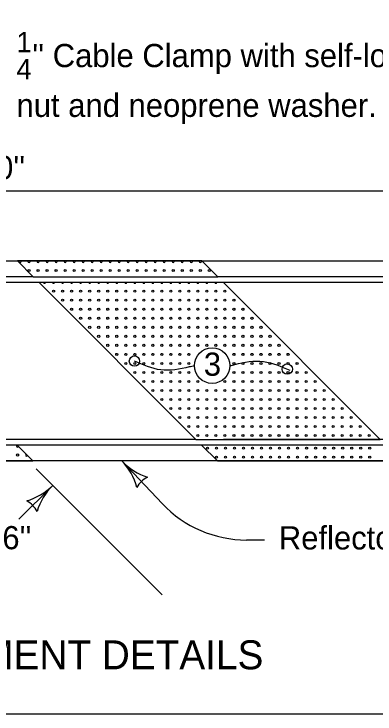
# Model space of a CAD drawing. Extents: x 228 to 3572, y -1307 to 1277.
# Drawn here: x 2207.4 to 2456.6, y -1020 to -537.2 of the extents above; entities that cross this region are included whole.
import ezdxf

# ---------------------------------------------------------------- set-up
doc = ezdxf.new("R2010")
doc.units = 0
for name, color, linetype in [('dsnStdBorder', 7, 'Continuous'), ('dsnStdDimension', 7, 'Continuous'), ('Level 2', 7, 'Continuous'), ('Level 3', 7, 'Continuous')]:
    doc.layers.add(name, color=color, linetype=linetype)

msp = doc.modelspace()

# ---------------------------------------------------------------- linework, layer by layer
at = {"layer": 'dsnStdBorder'}
msp.add_lwpolyline([(332.48, 990.01), (3467.48, 990.01), (3467.48, -1019.99), (332.48, -1019.99)], close=True, dxfattribs=at)
at = {"layer": 'dsnStdDimension'}
for p, q in [((2559.99, -659.46), (1827.99, -659.46)), ((2309.83, -874.95), (2281.94, -845.46)), ((2309.76, -937.89), (2222.85, -850.98)), ((2210.76, -885.69), (2234.16, -862.29)), ((2380.35, -899.98), (2367.96, -899.98))]:
    msp.add_line(p, q, dxfattribs=at)
for centre, radius, start, end in [((2313.31, -815.79), 43.18, 223.3968, 251.4693), ((2250.56, -875.12), 43.18, 15.3243, 43.3968), ((2306.81, -871.76), 16.68, 115.6635, 151.1302), ((2203.63, -831.76), 43.18, 286.9275, 315), ((2264.69, -892.83), 43.18, 135, 163.0725), ((2208.56, -887.89), 16.68, 27.2667, 62.7334), ((2367.95, -819.98), 80, 223.3989, 270)]:
    msp.add_arc(centre, radius, start, end, dxfattribs=at)
at = {"layer": 'Level 2'}
for p, q in [((2337.11, -707.46), (2209.83, -707.46)), ((2209.83, -707.46), (2220.73, -718.36)), ((2220.55, -707.46), (2347.83, -707.46)), ((2348.01, -718.36), (2337.11, -707.46)), ((2220.73, -718.36), (2093.45, -718.36)), ((2220.73, -718.36), (2348.01, -718.36)), ((2475.29, -718.36), (2348.01, -718.36)), ((2224.73, -722.36), (2097.45, -722.36)), ((2352.01, -722.36), (2224.73, -722.36)), ((2224.73, -722.36), (2332.93, -830.56)), ((2460.21, -830.56), (2352.01, -722.36)), ((2479.29, -722.36), (2352.01, -722.36)), ((2209.65, -834.56), (2082.37, -834.56)), ((2336.93, -834.56), (2093.45, -834.56)), ((2332.93, -830.56), (2097.45, -830.56)), ((2220.55, -845.46), (2209.65, -834.56)), ((2332.93, -830.56), (2460.21, -830.56)), ((2464.21, -834.56), (2336.93, -834.56)), ((2336.93, -834.56), (2347.83, -845.46)), ((2527.59, -834.56), (2348.01, -834.56)), ((2527.59, -830.56), (2352.01, -830.56)), ((2209.83, -845.46), (1960.08, -845.46)), ((2093.27, -845.46), (2220.55, -845.46)), ((2464.39, -845.46), (2337.11, -845.46)), ((2347.83, -845.46), (2475.11, -845.46))]:
    msp.add_line(p, q, dxfattribs=at)
msp.add_lwpolyline([(1827.99, -707.46), (2559.99, -707.46), (2559.99, -845.46), (1827.99, -845.46)], close=True, dxfattribs=at)
for centre, radius in [((2217.8, -714.12), 0.711), ((2224.03, -714.12), 0.711), ((2230.25, -714.12), 0.711), ((2236.47, -714.12), 0.711), ((2242.69, -714.12), 0.711), ((2248.92, -714.12), 0.711), ((2255.14, -714.12), 0.711), ((2261.36, -714.12), 0.711), ((2267.58, -714.12), 0.711), ((2273.81, -714.12), 0.711), ((2280.03, -714.12), 0.711), ((2286.25, -714.12), 0.711), ((2292.47, -714.12), 0.711), ((2298.7, -714.12), 0.711), ((2304.92, -714.12), 0.711), ((2311.14, -714.12), 0.711), ((2317.36, -714.12), 0.711), ((2323.58, -714.12), 0.711), ((2329.81, -714.12), 0.711), ((2336.03, -714.12), 0.711), ((2342.25, -714.12), 0.711), ((2234.78, -728.38), 0.711), ((2241, -728.38), 0.711), ((2247.22, -728.38), 0.711), ((2253.44, -728.38), 0.711), ((2259.67, -728.38), 0.711), ((2265.89, -728.38), 0.711), ((2272.11, -728.38), 0.711), ((2278.33, -728.38), 0.711), ((2284.56, -728.38), 0.711), ((2290.78, -728.38), 0.711), ((2297, -728.38), 0.711), ((2303.22, -728.38), 0.711), ((2309.45, -728.38), 0.711), ((2315.67, -728.38), 0.711), ((2321.89, -728.38), 0.711), ((2328.11, -728.38), 0.711), ((2334.34, -728.38), 0.711), ((2340.56, -728.38), 0.711), ((2346.78, -728.38), 0.711), ((2353, -728.38), 0.711), ((2241, -734.6), 0.711), ((2247.22, -734.6), 0.711), ((2253.44, -734.6), 0.711), ((2259.67, -734.6), 0.711), ((2265.89, -734.6), 0.711), ((2272.11, -734.6), 0.711), ((2278.33, -734.6), 0.711), ((2284.56, -734.6), 0.711), ((2290.78, -734.6), 0.711), ((2297, -734.6), 0.711), ((2303.22, -734.6), 0.711), ((2309.45, -734.6), 0.711), ((2315.67, -734.6), 0.711), ((2321.89, -734.6), 0.711), ((2328.11, -734.6), 0.711), ((2334.34, -734.6), 0.711), ((2340.56, -734.6), 0.711), ((2346.78, -734.6), 0.711), ((2353, -734.6), 0.711), ((2359.23, -734.6), 0.711), ((2247.22, -740.83), 0.711), ((2253.44, -740.83), 0.711), ((2259.67, -740.83), 0.711), ((2265.89, -740.83), 0.711), ((2272.11, -740.83), 0.711), ((2278.33, -740.83), 0.711), ((2284.56, -740.83), 0.711), ((2290.78, -740.83), 0.711), ((2297, -740.83), 0.711), ((2303.22, -740.83), 0.711), ((2309.45, -740.83), 0.711), ((2315.67, -740.83), 0.711), ((2321.89, -740.83), 0.711), ((2328.11, -740.83), 0.711), ((2334.34, -740.83), 0.711), ((2340.56, -740.83), 0.711), ((2346.78, -740.83), 0.711), ((2353, -740.83), 0.711), ((2359.23, -740.83), 0.711), ((2365.45, -740.83), 0.711), ((2253.44, -747.05), 0.711), ((2259.67, -747.05), 0.711), ((2265.89, -747.05), 0.711), ((2272.11, -747.05), 0.711), ((2278.33, -747.05), 0.711), ((2284.56, -747.05), 0.711), ((2290.78, -747.05), 0.711), ((2297, -747.05), 0.711), ((2303.22, -747.05), 0.711), ((2309.45, -747.05), 0.711), ((2315.67, -747.05), 0.711), ((2321.89, -747.05), 0.711), ((2328.11, -747.05), 0.711), ((2334.34, -747.05), 0.711), ((2340.56, -747.05), 0.711), ((2346.78, -747.05), 0.711), ((2353, -747.05), 0.711), ((2359.23, -747.05), 0.711), ((2365.45, -747.05), 0.711), ((2371.67, -747.05), 0.711), ((2259.67, -753.27), 0.711), ((2265.89, -753.27), 0.711), ((2272.11, -753.27), 0.711), ((2278.33, -753.27), 0.711), ((2284.56, -753.27), 0.711), ((2290.78, -753.27), 0.711), ((2297, -753.27), 0.711), ((2303.22, -753.27), 0.711), ((2309.45, -753.27), 0.711), ((2315.67, -753.27), 0.711), ((2321.89, -753.27), 0.711), ((2328.11, -753.27), 0.711), ((2334.34, -753.27), 0.711), ((2340.56, -753.27), 0.711), ((2346.78, -753.27), 0.711), ((2353, -753.27), 0.711), ((2359.23, -753.27), 0.711), ((2365.45, -753.27), 0.711), ((2371.67, -753.27), 0.711), ((2377.89, -753.27), 0.711), ((2265.89, -759.49), 0.711), ((2272.11, -759.49), 0.711), ((2278.33, -759.49), 0.711), ((2284.56, -759.49), 0.711), ((2290.78, -759.49), 0.711), ((2297, -759.49), 0.711), ((2303.22, -759.49), 0.711), ((2309.45, -759.49), 0.711), ((2315.67, -759.49), 0.711), ((2321.89, -759.49), 0.711), ((2328.11, -759.49), 0.711), ((2334.34, -759.49), 0.711), ((2340.56, -759.49), 0.711), ((2346.78, -759.49), 0.711), ((2353, -759.49), 0.711), ((2359.23, -759.49), 0.711), ((2365.45, -759.49), 0.711), ((2371.67, -759.49), 0.711), ((2377.89, -759.49), 0.711), ((2384.12, -759.49), 0.711), ((2272.11, -765.72), 0.711), ((2278.33, -765.72), 0.711), ((2284.56, -765.72), 0.711), ((2290.78, -765.72), 0.711), ((2297, -765.72), 0.711), ((2303.22, -765.72), 0.711), ((2309.45, -765.72), 0.711), ((2315.67, -765.72), 0.711), ((2321.89, -765.72), 0.711), ((2328.11, -765.72), 0.711), ((2344.17, -779.7), 12.25), ((2334.34, -765.72), 0.711), ((2340.56, -765.72), 0.711), ((2346.78, -765.72), 0.711), ((2353, -765.72), 0.711), ((2359.23, -765.72), 0.711), ((2365.45, -765.72), 0.711), ((2371.67, -765.72), 0.711), ((2377.89, -765.72), 0.711), ((2384.12, -765.72), 0.711), ((2390.34, -765.72), 0.711), ((2278.33, -771.94), 0.711), ((2284.56, -771.94), 0.711), ((2290.78, -771.94), 0.711), ((2297, -771.94), 0.711), ((2303.22, -771.94), 0.711), ((2309.45, -771.94), 0.711), ((2315.67, -771.94), 0.711), ((2321.89, -771.94), 0.711), ((2328.11, -771.94), 0.711), ((2359.23, -771.94), 0.711), ((2365.45, -771.94), 0.711), ((2371.67, -771.94), 0.711), ((2377.89, -771.94), 0.711), ((2384.12, -771.94), 0.711), ((2390.34, -771.94), 0.711), ((2396.56, -771.94), 0.711), ((2290.58, -776.56), 3.56), ((2284.56, -778.16), 0.711), ((2290.76, -778.21), 0.711), ((2297, -778.16), 0.711), ((2303.22, -778.16), 0.711), ((2309.45, -778.16), 0.711), ((2315.67, -778.16), 0.711), ((2321.89, -778.16), 0.711), ((2328.11, -778.16), 0.711), ((2359.23, -778.16), 0.711), ((2365.45, -778.16), 0.711), ((2371.67, -778.16), 0.711), ((2377.89, -778.16), 0.711), ((2384.12, -778.16), 0.711), ((2390.34, -778.16), 0.711), ((2396.04, -782.04), 3.56), ((2396.56, -778.16), 0.711), ((2402.78, -778.16), 0.711), ((2290.78, -784.38), 0.711), ((2297, -784.38), 0.711), ((2303.22, -784.38), 0.711), ((2309.45, -784.38), 0.711), ((2315.67, -784.38), 0.711), ((2321.89, -784.38), 0.711), ((2328.11, -784.38), 0.711), ((2359.23, -784.38), 0.711), ((2365.45, -784.38), 0.711), ((2371.67, -784.38), 0.711), ((2377.89, -784.38), 0.711), ((2384.12, -784.38), 0.711), ((2390.34, -784.38), 0.711), ((2396.54, -784.43), 0.711), ((2402.78, -784.38), 0.711), ((2409, -784.38), 0.711), ((2297, -790.61), 0.711), ((2303.22, -790.61), 0.711), ((2309.45, -790.61), 0.711), ((2315.67, -790.61), 0.711), ((2321.89, -790.61), 0.711), ((2328.11, -790.61), 0.711), ((2334.34, -790.61), 0.711), ((2353, -790.61), 0.711), ((2359.23, -790.61), 0.711), ((2365.45, -790.61), 0.711), ((2371.67, -790.61), 0.711), ((2377.89, -790.61), 0.711), ((2384.12, -790.61), 0.711), ((2390.34, -790.61), 0.711), ((2396.56, -790.61), 0.711), ((2402.78, -790.61), 0.711), ((2409, -790.61), 0.711), ((2415.23, -790.61), 0.711), ((2303.22, -796.83), 0.711), ((2309.45, -796.83), 0.711), ((2315.67, -796.83), 0.711), ((2321.89, -796.83), 0.711), ((2328.11, -796.83), 0.711), ((2334.34, -796.83), 0.711), ((2340.56, -796.83), 0.711), ((2346.78, -796.83), 0.711), ((2353, -796.83), 0.711), ((2359.23, -796.83), 0.711), ((2365.45, -796.83), 0.711), ((2371.67, -796.83), 0.711), ((2377.89, -796.83), 0.711), ((2384.12, -796.83), 0.711), ((2390.34, -796.83), 0.711), ((2396.56, -796.83), 0.711), ((2402.78, -796.83), 0.711), ((2409, -796.83), 0.711), ((2415.23, -796.83), 0.711), ((2421.45, -796.83), 0.711), ((2309.45, -803.05), 0.711), ((2315.67, -803.05), 0.711), ((2321.89, -803.05), 0.711), ((2328.11, -803.05), 0.711), ((2334.34, -803.05), 0.711), ((2340.56, -803.05), 0.711), ((2346.78, -803.05), 0.711), ((2353, -803.05), 0.711), ((2359.23, -803.05), 0.711), ((2365.45, -803.05), 0.711), ((2371.67, -803.05), 0.711), ((2377.89, -803.05), 0.711), ((2384.12, -803.05), 0.711), ((2390.34, -803.05), 0.711), ((2396.56, -803.05), 0.711), ((2402.78, -803.05), 0.711), ((2409, -803.05), 0.711), ((2415.23, -803.05), 0.711), ((2421.45, -803.05), 0.711), ((2427.67, -803.05), 0.711), ((2315.67, -809.27), 0.711), ((2321.89, -809.27), 0.711), ((2328.11, -809.27), 0.711), ((2334.34, -809.27), 0.711), ((2340.56, -809.27), 0.711), ((2346.78, -809.27), 0.711), ((2353, -809.27), 0.711), ((2359.23, -809.27), 0.711), ((2365.45, -809.27), 0.711), ((2371.67, -809.27), 0.711), ((2377.89, -809.27), 0.711), ((2384.12, -809.27), 0.711), ((2390.34, -809.27), 0.711), ((2396.56, -809.27), 0.711), ((2402.78, -809.27), 0.711), ((2409, -809.27), 0.711), ((2415.23, -809.27), 0.711), ((2421.45, -809.27), 0.711), ((2427.67, -809.27), 0.711), ((2433.89, -809.27), 0.711), ((2321.89, -815.5), 0.711), ((2328.11, -815.5), 0.711), ((2334.34, -815.5), 0.711), ((2340.56, -815.5), 0.711), ((2346.78, -815.5), 0.711), ((2353, -815.5), 0.711), ((2359.23, -815.5), 0.711), ((2365.45, -815.5), 0.711), ((2371.67, -815.5), 0.711), ((2377.89, -815.5), 0.711), ((2384.12, -815.5), 0.711), ((2390.34, -815.5), 0.711), ((2396.56, -815.5), 0.711), ((2402.78, -815.5), 0.711), ((2409, -815.5), 0.711), ((2415.23, -815.5), 0.711), ((2421.45, -815.5), 0.711), ((2427.67, -815.5), 0.711), ((2433.89, -815.5), 0.711), ((2440.12, -815.5), 0.711), ((2328.11, -821.72), 0.711), ((2334.34, -821.72), 0.711), ((2340.56, -821.72), 0.711), ((2346.78, -821.72), 0.711), ((2353, -821.72), 0.711), ((2359.23, -821.72), 0.711), ((2365.45, -821.72), 0.711), ((2371.67, -821.72), 0.711), ((2377.89, -821.72), 0.711), ((2384.12, -821.72), 0.711), ((2390.34, -821.72), 0.711), ((2396.56, -821.72), 0.711), ((2402.78, -821.72), 0.711), ((2409, -821.72), 0.711), ((2415.23, -821.72), 0.711), ((2421.45, -821.72), 0.711), ((2427.67, -821.72), 0.711), ((2433.89, -821.72), 0.711), ((2440.12, -821.72), 0.711), ((2446.34, -821.72), 0.711), ((2334.34, -827.94), 0.711), ((2340.56, -827.94), 0.711), ((2346.78, -827.94), 0.711), ((2353, -827.94), 0.711), ((2359.23, -827.94), 0.711), ((2365.45, -827.94), 0.711), ((2371.67, -827.94), 0.711), ((2377.89, -827.94), 0.711), ((2384.12, -827.94), 0.711), ((2390.34, -827.94), 0.711), ((2396.56, -827.94), 0.711), ((2402.78, -827.94), 0.711), ((2409, -827.94), 0.711), ((2415.23, -827.94), 0.711), ((2421.45, -827.94), 0.711), ((2427.67, -827.94), 0.711), ((2433.89, -827.94), 0.711), ((2440.12, -827.94), 0.711), ((2446.34, -827.94), 0.711), ((2452.56, -827.94), 0.711), ((2340.93, -836.67), 0.711), ((2347.15, -836.67), 0.711), ((2353.37, -836.67), 0.711), ((2359.6, -836.67), 0.711), ((2365.82, -836.67), 0.711), ((2372.04, -836.67), 0.711), ((2378.26, -836.67), 0.711), ((2384.49, -836.67), 0.711), ((2390.71, -836.67), 0.711), ((2396.93, -836.67), 0.711), ((2403.15, -836.67), 0.711), ((2409.38, -836.67), 0.711), ((2415.6, -836.67), 0.711), ((2421.82, -836.67), 0.711), ((2428.04, -836.67), 0.711), ((2434.27, -836.67), 0.711), ((2440.49, -836.67), 0.711), ((2446.71, -836.67), 0.711), ((2452.93, -836.67), 0.711), ((2209.95, -841.35), 0.711), ((2347.15, -842.9), 0.711), ((2353.37, -842.9), 0.711), ((2359.6, -842.9), 0.711), ((2365.82, -842.9), 0.711), ((2372.04, -842.9), 0.711), ((2378.26, -842.9), 0.711), ((2384.49, -842.9), 0.711), ((2390.71, -842.9), 0.711), ((2396.93, -842.9), 0.711), ((2403.15, -842.9), 0.711), ((2409.38, -842.9), 0.711), ((2415.6, -842.9), 0.711), ((2421.82, -842.9), 0.711), ((2428.04, -842.9), 0.711), ((2434.27, -842.9), 0.711), ((2440.49, -842.9), 0.711), ((2446.71, -842.9), 0.711), ((2452.93, -842.9), 0.711)]:
    msp.add_circle(centre, radius, dxfattribs=at)
for centre, start, end in [((2211.58, -707.9), 141.3696, 38.6304), ((2217.8, -707.9), 141.3696, 38.6304), ((2224.03, -707.9), 141.3696, 38.6304), ((2230.25, -707.9), 141.3696, 38.6304), ((2236.47, -707.9), 141.3696, 38.6304), ((2242.69, -707.9), 141.3696, 38.6304), ((2248.92, -707.9), 141.3696, 38.6304), ((2255.14, -707.9), 141.3696, 38.6304), ((2261.36, -707.9), 141.3696, 38.6304), ((2267.58, -707.9), 141.3696, 38.6304), ((2273.81, -707.9), 141.3696, 38.6304), ((2280.03, -707.9), 141.3696, 38.6304), ((2286.25, -707.9), 141.3696, 38.6304), ((2292.47, -707.9), 141.3696, 38.6304), ((2298.7, -707.9), 141.3696, 38.6304), ((2304.92, -707.9), 141.3696, 38.6304), ((2311.14, -707.9), 141.3696, 38.6304), ((2317.36, -707.9), 141.3696, 38.6304), ((2323.58, -707.9), 141.3696, 38.6304), ((2329.81, -707.9), 141.3696, 38.6304), ((2336.03, -707.9), 141.3696, 38.6304), ((2228.56, -722.16), 195.9974, 344.0026), ((2234.78, -722.16), 195.9974, 344.0026), ((2241, -722.16), 195.9974, 344.0026), ((2247.22, -722.16), 195.9974, 344.0026), ((2253.44, -722.16), 195.9974, 344.0026), ((2259.67, -722.16), 195.9974, 344.0026), ((2265.89, -722.16), 195.9974, 344.0026), ((2272.11, -722.16), 195.9974, 344.0026), ((2278.33, -722.16), 195.9974, 344.0026), ((2284.56, -722.16), 195.9974, 344.0026), ((2290.78, -722.16), 195.9974, 344.0026), ((2297, -722.16), 195.9974, 344.0026), ((2303.22, -722.16), 195.9974, 344.0026), ((2309.45, -722.16), 195.9974, 344.0026), ((2315.67, -722.16), 195.9974, 344.0026), ((2321.89, -722.16), 195.9974, 344.0026), ((2328.11, -722.16), 195.9974, 344.0026), ((2334.34, -722.16), 195.9974, 344.0026), ((2340.56, -722.16), 195.9974, 344.0026), ((2346.78, -722.16), 195.9974, 344.0026), ((2209.95, -835.13), 126.6764, 330.7375), ((2216.17, -841.35), 119.2625, 330.7375)]:
    msp.add_arc(centre, 0.711, start, end, dxfattribs=at)
for points in [[(2331.92, -779.74), (2328.36, -780.64), (2308.71, -782.66), (2290.57, -776.55)], [(2356.49, -779.72), (2359.93, -778.85), (2379.58, -776.83), (2397.73, -782.94)]]:
    msp.add_spline(points, degree=3, dxfattribs=at)

# ---------------------------------------------------------------- texts
at = {"layer": 'dsnStdDimension'}
for s, height, p in [('1', 14, (2209.18, -563.49)), ("'' Cable Clamp with self-locking", 16, (2220.05, -573.82)), ('4', 14, (2209.18, -582.15)), ('nut and neoprene washer.', 16, (2209.18, -608.15)), ("4'-0''", 16, (2171.96, -651.07)), ("6''", 16, (2199.4, -906.35)), ('Reflectorized', 16, (2390.19, -906.5))]:
    msp.add_text(s, height=height, dxfattribs=at).set_placement(p)
at = {"layer": 'Level 3'}
for s, height, p in [('3', 16, (2338.44, -786.69)), ('PANEL ATTACHMENT DETAILS', 20, (1982.75, -989.16))]:
    msp.add_text(s, height=height, dxfattribs=at).set_placement(p)

doc.saveas('drawing.dxf')
